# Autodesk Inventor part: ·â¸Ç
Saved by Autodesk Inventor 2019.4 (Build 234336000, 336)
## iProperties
Created: 2020-05
Part Number: ·â¸Ç
Material: Generic
Document SubType Name: Modeling
Designer: Administrator
Density: 1 g/cm^3
Appearance: Default
Title: ·â¸Ç
Author: Administrator
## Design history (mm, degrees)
feature "Body1"
body "Solid1"
